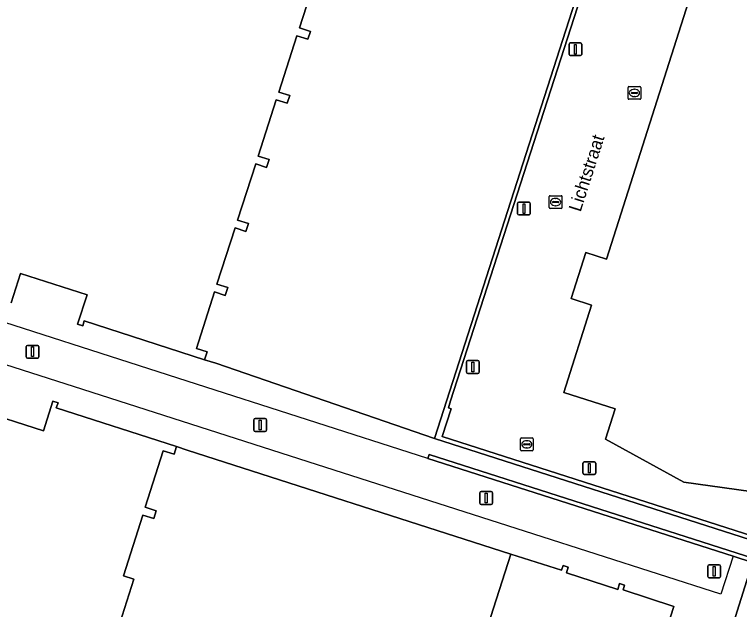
# Model space of a CAD drawing. Extents: x 160675 to 161153, y 383241 to 383714.
# Drawn here: x 160930.1 to 160986.7, y 383290.4 to 383336.8 of the extents above; entities that cross this region are included whole.
import ezdxf

# ---------------------------------------------------------------- set-up
doc = ezdxf.new("R2010")
doc.units = 0
for name, color, linetype in [('IMGEO_Brandkraan', 7, 'Continuous'), ('IMGEO_Erf', 7, 'Continuous'), ('IMGEO_Hek', 7, 'Continuous'), ('IMGEO_Kolk', 7, 'Continuous'), ('IMGEO_Lichtmast', 7, 'Continuous'), ('IMGEO_Lijnafwatering', 7, 'Continuous'), ('IMGEO_Muur', 7, 'Continuous'), ('IMGEO_Openbare_ruimte_label', 7, 'Continuous'), ('IMGEO_Pand', 7, 'Continuous'), ('IMGEO_Rijbaan_lokaal_open', 7, 'Continuous'), ('IMGEO_Rioolput', 7, 'Continuous'), ('IMGEO_Voetpad_open', 7, 'Continuous')]:
    doc.layers.add(name, color=color, linetype=linetype)

msp = doc.modelspace()

# ---------------------------------------------------------------- linework, layer by layer
at = {"layer": 'IMGEO_Brandkraan'}
for p, q in [((160971.832, 383321.719), (160971.832, 383322.571)), ((160971.907, 383322.645), (160972.759, 383322.645)), ((160972.833, 383322.571), (160972.833, 383321.719)), ((160972.091, 383322.139), (160972.091, 383322.151)), ((160972.529, 383322.102), (160972.131, 383322.102)), ((160972.134, 383322.188), (160972.532, 383322.188)), ((160972.32, 383322.425), (160972.345, 383322.425)), ((160972.575, 383322.151), (160972.575, 383322.139)), ((160972.759, 383321.645), (160971.907, 383321.645)), ((160972.343, 383321.865), (160972.318, 383321.865))]:
    msp.add_line(p, q, dxfattribs=at)
for points in [[(160971.832, 383321.719), (160971.832, 383322.571)], [(160971.907, 383322.645), (160972.759, 383322.645)], [(160972.833, 383322.571), (160972.833, 383321.719)], [(160972.759, 383321.645), (160971.907, 383321.645)]]:
    msp.add_lwpolyline(points, dxfattribs=at)
for centre, radius, start, end in [((160971.909, 383322.569), 0.0765, 91.552, 178.448), ((160971.909, 383322.569), 0.0765, 91.552, 178.448), ((160972.757, 383322.569), 0.0765, 1.552, 88.448), ((160972.757, 383322.569), 0.0765, 1.552, 88.448), ((160972.131, 383322.148), 0.0403, 85.8775, 175.7526), ((160972.128, 383322.138), 0.0366, 178.938, 274.7102), ((160972.532, 383322.145), 0.043, 264.8664, 352.4533), ((160972.536, 383322.15), 0.0386, 1.7309, 96.639), ((160971.909, 383321.721), 0.0765, 181.552, 268.448), ((160971.909, 383321.721), 0.0765, 181.552, 268.448), ((160972.757, 383321.721), 0.0765, 271.552, 358.448), ((160972.757, 383321.721), 0.0765, 271.552, 358.448)]:
    msp.add_arc(centre, radius, start, end, dxfattribs=at)
for centre, major_axis, ratio, start_param, end_param in [((160972.319, 383322.145), (-0.387, 0.002), 0.722429, 4.712389, 7.853982), ((160972.344, 383322.145), (-0.39, 0.002), 0.717154, 1.570796, 4.712389)]:
    msp.add_ellipse(centre, major_axis=major_axis, ratio=ratio, start_param=start_param, end_param=end_param, dxfattribs=at)
at = {"layer": 'IMGEO_Erf'}
msp.add_lwpolyline([(160953.771, 383340.116), (160952.365, 383335.733), (160953.213, 383335.462), (160953.015, 383334.857), (160952.167, 383335.128), (160950.757, 383330.733), (160951.605, 383330.462), (160951.399, 383329.857), (160950.551, 383330.128), (160949.145, 383325.732), (160949.993, 383325.461), (160949.796, 383324.85), (160948.948, 383325.121), (160947.536, 383320.743), (160948.384, 383320.472), (160948.187, 383319.857), (160947.339, 383320.128), (160945.92, 383315.754), (160946.768, 383315.483), (160946.575, 383314.867), (160945.727, 383315.138), (160944.319, 383310.732), (160945.167, 383310.461), (160944.96, 383309.85), (160945.837, 383309.589), (160962.889, 383303.693), (160979.089, 383354.099)], dxfattribs=at)
msp.add_lwpolyline([(160943.614, 383302.795), (160942.777, 383303.077), (160942.578, 383302.465), (160941.73, 383302.736), (160940.32, 383298.343), (160941.191, 383298.065), (160940.991, 383297.445), (160940.143, 383297.716), (160938.625, 383292.988), (160939.448, 383292.73), (160937.804, 383287.581), (160963.866, 383279.201), (160968.854, 383294.685)], close=True, dxfattribs=at)
at = {"layer": 'IMGEO_Hek'}
for points in [[(160945.837, 383309.589), (160962.889, 383303.693)], [(160968.854, 383294.685), (160943.614, 383302.795)]]:
    msp.add_lwpolyline(points, dxfattribs=at)
at = {"layer": 'IMGEO_Kolk'}
for p, q in [((160977.983, 383330.241), (160977.983, 383331.093)), ((160978.058, 383331.167), (160978.91, 383331.167)), ((160978.471, 383330.947), (160978.496, 383330.947)), ((160978.984, 383331.093), (160978.984, 383330.241)), ((160978.242, 383330.661), (160978.242, 383330.673)), ((160978.68, 383330.624), (160978.282, 383330.624)), ((160978.285, 383330.71), (160978.683, 383330.71)), ((160978.494, 383330.387), (160978.469, 383330.387)), ((160978.726, 383330.673), (160978.726, 383330.661)), ((160978.91, 383330.167), (160978.058, 383330.167))]:
    msp.add_line(p, q, dxfattribs=at)
for points in [[(160977.983, 383330.241), (160977.983, 383331.093)], [(160978.058, 383331.167), (160978.91, 383331.167)], [(160978.984, 383331.093), (160978.984, 383330.241)], [(160978.91, 383330.167), (160978.058, 383330.167)]]:
    msp.add_lwpolyline(points, dxfattribs=at)
for centre, radius, start, end in [((160978.06, 383331.091), 0.0765, 91.552, 178.448), ((160978.06, 383331.091), 0.0765, 91.552, 178.448), ((160978.908, 383331.091), 0.0765, 1.552, 88.448), ((160978.908, 383331.091), 0.0765, 1.552, 88.448), ((160978.282, 383330.67), 0.0403, 85.8775, 175.7526), ((160978.279, 383330.66), 0.0366, 178.938, 274.7102), ((160978.683, 383330.667), 0.043, 264.8664, 352.4533), ((160978.687, 383330.672), 0.0386, 1.7309, 96.639), ((160978.06, 383330.243), 0.0765, 181.552, 268.448), ((160978.06, 383330.243), 0.0765, 181.552, 268.448), ((160978.908, 383330.243), 0.0765, 271.552, 358.448), ((160978.908, 383330.243), 0.0765, 271.552, 358.448)]:
    msp.add_arc(centre, radius, start, end, dxfattribs=at)
for centre, major_axis, ratio, start_param, end_param in [((160978.47, 383330.667), (-0.387, 0.002), 0.722429, 4.712389, 7.853982), ((160978.495, 383330.667), (-0.39, 0.002), 0.717154, 1.570796, 4.712389)]:
    msp.add_ellipse(centre, major_axis=major_axis, ratio=ratio, start_param=start_param, end_param=end_param, dxfattribs=at)
at = {"layer": 'IMGEO_Lichtmast'}
for p, q in [((160973.38, 383333.673), (160973.38, 383334.473)), ((160973.38, 383334.473), (160973.38, 383333.673)), ((160973.48, 383334.573), (160974.27, 383334.573)), ((160974.27, 383334.573), (160973.48, 383334.573)), ((160974.37, 383334.473), (160974.37, 383333.673)), ((160974.37, 383333.673), (160974.37, 383334.473)), ((160974.27, 383333.573), (160973.48, 383333.573)), ((160973.48, 383333.573), (160974.27, 383333.573)), ((160969.372, 383321.243), (160969.372, 383322.043)), ((160969.372, 383322.043), (160969.372, 383321.243)), ((160969.472, 383322.143), (160970.262, 383322.143)), ((160970.262, 383322.143), (160969.472, 383322.143)), ((160970.362, 383322.043), (160970.362, 383321.243)), ((160970.362, 383321.243), (160970.362, 383322.043)), ((160970.262, 383321.143), (160969.472, 383321.143)), ((160969.472, 383321.143), (160970.262, 383321.143)), ((160931.054, 383310.066), (160931.054, 383310.866)), ((160931.054, 383310.866), (160931.054, 383310.066)), ((160931.154, 383310.966), (160931.944, 383310.966)), ((160931.944, 383310.966), (160931.154, 383310.966)), ((160932.044, 383310.866), (160932.044, 383310.066)), ((160932.044, 383310.066), (160932.044, 383310.866)), ((160931.944, 383309.966), (160931.154, 383309.966)), ((160931.154, 383309.966), (160931.944, 383309.966)), ((160965.386, 383308.88), (160965.386, 383309.68)), ((160965.386, 383309.68), (160965.386, 383308.88)), ((160965.486, 383309.78), (160966.276, 383309.78)), ((160966.276, 383309.78), (160965.486, 383309.78)), ((160966.376, 383309.68), (160966.376, 383308.88)), ((160966.376, 383308.88), (160966.376, 383309.68)), ((160966.276, 383308.78), (160965.486, 383308.78)), ((160965.486, 383308.78), (160966.276, 383308.78)), ((160948.802, 383304.352), (160948.802, 383305.152)), ((160948.802, 383305.152), (160948.802, 383304.352)), ((160948.902, 383305.252), (160949.692, 383305.252)), ((160949.692, 383305.252), (160948.902, 383305.252)), ((160949.792, 383305.152), (160949.792, 383304.352)), ((160949.792, 383304.352), (160949.792, 383305.152)), ((160949.692, 383304.252), (160948.902, 383304.252)), ((160948.902, 383304.252), (160949.692, 383304.252)), ((160974.469, 383300.985), (160974.469, 383301.785)), ((160974.469, 383301.785), (160974.469, 383300.985)), ((160974.569, 383301.885), (160975.359, 383301.885)), ((160975.359, 383301.885), (160974.569, 383301.885)), ((160975.459, 383301.785), (160975.459, 383300.985)), ((160975.459, 383300.985), (160975.459, 383301.785)), ((160975.359, 383300.885), (160974.569, 383300.885)), ((160974.569, 383300.885), (160975.359, 383300.885)), ((160966.428, 383298.656), (160966.428, 383299.456)), ((160966.428, 383299.456), (160966.428, 383298.656)), ((160966.528, 383299.556), (160967.318, 383299.556)), ((160967.318, 383299.556), (160966.528, 383299.556)), ((160967.418, 383299.456), (160967.418, 383298.656)), ((160967.418, 383298.656), (160967.418, 383299.456)), ((160967.318, 383298.556), (160966.528, 383298.556)), ((160966.528, 383298.556), (160967.318, 383298.556)), ((160984.2, 383292.938), (160984.2, 383293.738)), ((160984.2, 383293.738), (160984.2, 383292.938)), ((160984.3, 383293.838), (160985.09, 383293.838)), ((160985.09, 383293.838), (160984.3, 383293.838)), ((160985.19, 383293.738), (160985.19, 383292.938)), ((160985.19, 383292.938), (160985.19, 383293.738)), ((160985.09, 383292.838), (160984.3, 383292.838)), ((160984.3, 383292.838), (160985.09, 383292.838))]:
    msp.add_line(p, q, dxfattribs=at)
for points in [[(160973.8, 383334.448), (160973.95, 383334.448), (160973.95, 383333.698), (160973.8, 383333.698), (160973.8, 383334.448)], [(160969.792, 383322.018), (160969.942, 383322.018), (160969.942, 383321.268), (160969.792, 383321.268), (160969.792, 383322.018)], [(160931.474, 383310.841), (160931.624, 383310.841), (160931.624, 383310.091), (160931.474, 383310.091), (160931.474, 383310.841)], [(160965.806, 383309.655), (160965.956, 383309.655), (160965.956, 383308.905), (160965.806, 383308.905), (160965.806, 383309.655)], [(160949.222, 383305.127), (160949.372, 383305.127), (160949.372, 383304.377), (160949.222, 383304.377), (160949.222, 383305.127)], [(160974.889, 383301.76), (160975.039, 383301.76), (160975.039, 383301.01), (160974.889, 383301.01), (160974.889, 383301.76)], [(160966.848, 383299.431), (160966.998, 383299.431), (160966.998, 383298.681), (160966.848, 383298.681), (160966.848, 383299.431)], [(160984.62, 383293.713), (160984.77, 383293.713), (160984.77, 383292.963), (160984.62, 383292.963), (160984.62, 383293.713)]]:
    msp.add_lwpolyline(points, dxfattribs=at)
for centre, start, end in [((160973.48, 383334.473), 90, 180), ((160973.48, 383334.473), 90, 180), ((160974.27, 383334.473), 0, 90), ((160974.27, 383334.473), 360, 90), ((160973.48, 383333.673), 180, 270), ((160973.48, 383333.673), 180, 270), ((160974.27, 383333.673), 270, 0), ((160974.27, 383333.673), 270, 0), ((160969.472, 383322.043), 90, 180), ((160969.472, 383322.043), 90, 180), ((160970.262, 383322.043), 0, 90), ((160970.262, 383322.043), 360, 90), ((160969.472, 383321.243), 180, 270), ((160969.472, 383321.243), 180, 270), ((160970.262, 383321.243), 270, 0), ((160970.262, 383321.243), 270, 0), ((160931.154, 383310.866), 90, 180), ((160931.154, 383310.866), 90, 180), ((160931.944, 383310.866), 0, 90), ((160931.944, 383310.866), 360, 90), ((160931.154, 383310.066), 180, 270), ((160931.154, 383310.066), 180, 270), ((160931.944, 383310.066), 270, 0), ((160931.944, 383310.066), 270, 0), ((160965.486, 383309.68), 90, 180), ((160965.486, 383309.68), 90, 180), ((160966.276, 383309.68), 0, 90), ((160966.276, 383309.68), 360, 90), ((160965.486, 383308.88), 180, 270), ((160965.486, 383308.88), 180, 270), ((160966.276, 383308.88), 270, 0), ((160966.276, 383308.88), 270, 0), ((160948.902, 383305.152), 90, 180), ((160948.902, 383305.152), 90, 180), ((160949.692, 383305.152), 0, 90), ((160949.692, 383305.152), 360, 90), ((160948.902, 383304.352), 180, 270), ((160948.902, 383304.352), 180, 270), ((160949.692, 383304.352), 270, 0), ((160949.692, 383304.352), 270, 0), ((160974.569, 383301.785), 90, 180), ((160974.569, 383301.785), 90, 180), ((160975.359, 383301.785), 0, 90), ((160975.359, 383301.785), 360, 90), ((160974.569, 383300.985), 180, 270), ((160974.569, 383300.985), 180, 270), ((160975.359, 383300.985), 270, 0), ((160975.359, 383300.985), 270, 0), ((160966.528, 383299.456), 90, 180), ((160966.528, 383299.456), 90, 180), ((160967.318, 383299.456), 0, 90), ((160967.318, 383299.456), 360, 90), ((160966.528, 383298.656), 180, 270), ((160966.528, 383298.656), 180, 270), ((160967.318, 383298.656), 270, 0), ((160967.318, 383298.656), 270, 0), ((160984.3, 383293.738), 90, 180), ((160984.3, 383293.738), 90, 180), ((160985.09, 383293.738), 0, 90), ((160985.09, 383293.738), 360, 90), ((160984.3, 383292.938), 180, 270), ((160984.3, 383292.938), 180, 270), ((160985.09, 383292.938), 270, 0), ((160985.09, 383292.938), 270, 0)]:
    msp.add_arc(centre, 0.1, start, end, dxfattribs=at)
at = {"layer": 'IMGEO_Lijnafwatering'}
for points in [[(160943.595, 383308.182), (160924.823, 383314.218)], [(160935.473, 383307.516), (160918.647, 383312.918), (160917.898, 383313.159)], [(160962.368, 383302.146), (160943.595, 383308.182)], [(160953.049, 383301.873), (160935.473, 383307.516)], [(160970.624, 383296.23), (160953.049, 383301.873)], [(160986.194, 383294.511), (160985.227, 383291.542), (160970.624, 383296.23)]]:
    msp.add_lwpolyline(points, dxfattribs=at)
at = {"layer": 'IMGEO_Muur'}
for points in [[(160944.96, 383309.85), (160945.837, 383309.589)], [(160943.614, 383302.795), (160942.777, 383303.077)]]:
    msp.add_lwpolyline(points, dxfattribs=at)
msp.add_lwpolyline([(160992.079, 383292.966), (160987.798, 383294.336), (160962.468, 383302.443), (160962.368, 383302.146), (160986.194, 383294.511), (160987.7, 383294.03), (160992.001, 383292.648)], close=True, dxfattribs=at)
at = {"layer": 'IMGEO_Pand'}
for points in [[(160989.634, 383359.598), (160976.293, 383317.706), (160974.69, 383318.217), (160973.542, 383314.614), (160975.14, 383314.105), (160972.968, 383307.284), (160976.986, 383306.005), (160976.237, 383303.65), (160982.34, 383300.282), (160989.622, 383299.281)], [(160929.868, 383314.28), (160930.61, 383316.584), (160935.799, 383314.916), (160935.057, 383312.612), (160935.469, 383312.483), (160935.57, 383312.891), (160944.96, 383309.85), (160945.167, 383310.461), (160944.319, 383310.732), (160945.727, 383315.138), (160946.575, 383314.867), (160946.768, 383315.483), (160945.92, 383315.754), (160947.339, 383320.128), (160948.187, 383319.857), (160948.384, 383320.472), (160947.536, 383320.743), (160948.948, 383325.121), (160949.796, 383324.85), (160949.993, 383325.461), (160949.145, 383325.732), (160950.551, 383330.128), (160951.399, 383329.857), (160951.605, 383330.462), (160950.757, 383330.733), (160952.167, 383335.128), (160953.015, 383334.857), (160953.213, 383335.462), (160952.365, 383335.733), (160953.771, 383340.116)], [(160920.037, 383273.784), (160958.187, 383268.56), (160960.344, 383268.267), (160963.866, 383279.201), (160937.804, 383287.581), (160939.448, 383292.73), (160938.625, 383292.988), (160940.143, 383297.716), (160940.991, 383297.445), (160941.191, 383298.065), (160940.32, 383298.343), (160941.73, 383302.736), (160942.578, 383302.465), (160942.777, 383303.077), (160933.386, 383306.103), (160933.536, 383306.474), (160933.134, 383306.606), (160932.393, 383304.302), (160927.197, 383305.975)], [(160975.365, 383277.155), (160976.425, 383280.494), (160978.117, 383279.956), (160981.552, 383290.599), (160977.592, 383291.879), (160977.719, 383292.257), (160977.324, 383292.384), (160977.178, 383291.927), (160973.174, 383293.215), (160973.324, 383293.671), (160972.929, 383293.801), (160972.807, 383293.43), (160968.854, 383294.685), (160963.866, 383279.201), (160960.344, 383268.267), (160973.818, 383266.439), (160987.295, 383264.611), (160985.535, 383267.741)]]:
    msp.add_lwpolyline(points, dxfattribs=at)
at = {"layer": 'IMGEO_Rijbaan_lokaal_open'}
msp.add_lwpolyline([(160989.634, 383359.598), (160988.097, 383360.087), (160988.884, 383362.56), (160983.014, 383364.509), (160979.608, 383353.93), (160979.448, 383353.431), (160979.25, 383353.51), (160964.138, 383306.646), (160963.969, 383306.082), (160964.19, 383306.014), (160963.499, 383303.848), (160992.588, 383294.531), (160994.422, 383300.461), (160990.405, 383301.74), (160989.622, 383299.281), (160982.34, 383300.282), (160976.237, 383303.65), (160976.986, 383306.005), (160972.968, 383307.284), (160975.14, 383314.105), (160973.542, 383314.614), (160974.69, 383318.217), (160976.293, 383317.706)], close=True, dxfattribs=at)
at = {"layer": 'IMGEO_Rioolput'}
for p, q in [((160969.591, 383302.824), (160969.591, 383303.676)), ((160969.666, 383303.75), (160970.518, 383303.75)), ((160969.85, 383303.244), (160969.85, 383303.256)), ((160969.893, 383303.293), (160970.291, 383303.293)), ((160970.079, 383303.53), (160970.104, 383303.53)), ((160970.334, 383303.256), (160970.334, 383303.244)), ((160970.592, 383303.676), (160970.592, 383302.824)), ((160970.518, 383302.75), (160969.666, 383302.75)), ((160970.288, 383303.207), (160969.89, 383303.207)), ((160970.102, 383302.97), (160970.077, 383302.97))]:
    msp.add_line(p, q, dxfattribs=at)
for points in [[(160969.591, 383302.824), (160969.591, 383303.676)], [(160969.666, 383303.75), (160970.518, 383303.75)], [(160970.592, 383303.676), (160970.592, 383302.824)], [(160970.518, 383302.75), (160969.666, 383302.75)]]:
    msp.add_lwpolyline(points, dxfattribs=at)
for centre, radius, start, end in [((160969.668, 383303.674), 0.0765, 91.552, 178.448), ((160969.668, 383303.674), 0.0765, 91.552, 178.448), ((160969.89, 383303.253), 0.0403, 85.8775, 175.7526), ((160969.887, 383303.243), 0.0366, 178.938, 274.7102), ((160970.291, 383303.25), 0.043, 264.8664, 352.4533), ((160970.295, 383303.255), 0.0386, 1.7309, 96.639), ((160970.516, 383303.674), 0.0765, 1.552, 88.448), ((160970.516, 383303.674), 0.0765, 1.552, 88.448), ((160969.668, 383302.826), 0.0765, 181.552, 268.448), ((160969.668, 383302.826), 0.0765, 181.552, 268.448), ((160970.516, 383302.826), 0.0765, 271.552, 358.448), ((160970.516, 383302.826), 0.0765, 271.552, 358.448)]:
    msp.add_arc(centre, radius, start, end, dxfattribs=at)
for centre, major_axis, ratio, start_param, end_param in [((160970.078, 383303.25), (-0.387, 0.002), 0.722429, 4.712389, 7.853982), ((160970.103, 383303.25), (-0.39, 0.002), 0.717154, 1.570796, 4.712389)]:
    msp.add_ellipse(centre, major_axis=major_axis, ratio=ratio, start_param=start_param, end_param=end_param, dxfattribs=at)
at = {"layer": 'IMGEO_Voetpad_open'}
for points in [[(160988.196, 383295.585), (160992.503, 383294.205), (160992.588, 383294.531), (160963.499, 383303.848), (160964.19, 383306.014), (160963.969, 383306.082), (160964.138, 383306.646), (160979.25, 383353.51), (160979.448, 383353.431), (160979.608, 383353.93), (160979.089, 383354.099), (160962.889, 383303.693)], [(160992.001, 383292.648), (160987.7, 383294.03), (160986.202, 383289.329), (160990.482, 383287.946)]]:
    msp.add_lwpolyline(points, close=True, dxfattribs=at)
for points in [[(160935.57, 383312.891), (160935.469, 383312.483), (160935.057, 383312.612), (160935.799, 383314.916), (160930.61, 383316.584), (160929.868, 383314.28)], [(160981.028, 383273.124), (160985.89, 383288.35), (160985.595, 383288.418), (160985.898, 383289.425), (160986.202, 383289.329), (160987.7, 383294.03), (160986.194, 383294.511), (160962.368, 383302.146), (160962.468, 383302.443), (160987.798, 383294.336), (160988.196, 383295.585), (160962.889, 383303.693), (160945.837, 383309.589), (160944.96, 383309.85), (160935.57, 383312.891)], [(160927.197, 383305.975), (160932.393, 383304.302), (160933.134, 383306.606), (160933.536, 383306.474), (160933.386, 383306.103), (160942.777, 383303.077), (160943.614, 383302.795), (160968.854, 383294.685), (160972.807, 383293.43), (160972.929, 383293.801), (160973.324, 383293.671), (160973.174, 383293.215), (160977.178, 383291.927), (160977.324, 383292.384), (160977.719, 383292.257), (160977.592, 383291.879), (160981.552, 383290.599), (160978.117, 383279.956), (160976.425, 383280.494), (160975.365, 383277.155)]]:
    msp.add_lwpolyline(points, dxfattribs=at)

# ---------------------------------------------------------------- texts
at = {"layer": 'IMGEO_Openbare_ruimte_label'}
msp.add_text('Lichtstraat', height=1, rotation=72.2357, dxfattribs=at).set_placement((160974.278, 383321.327))

doc.saveas('drawing.dxf')
